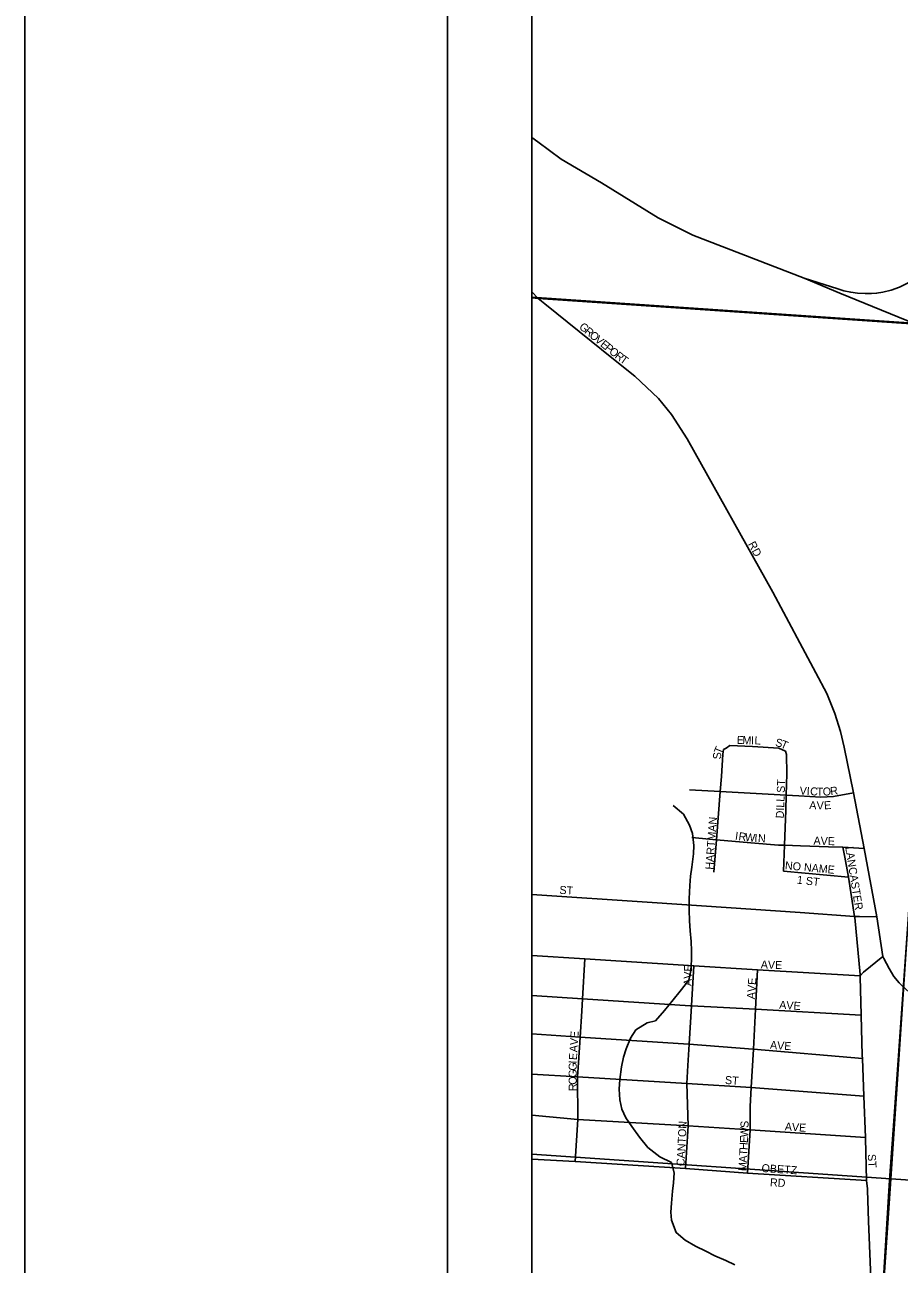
# Model space of a CAD drawing. Extents: x 0 to 34, y 0 to 22.
# Drawn here: x 2 to 3.034, y 15.158 to 16.625 of the extents above; entities that cross this region are included whole.
import ezdxf

# ---------------------------------------------------------------- set-up
doc = ezdxf.new("R2010")
doc.units = 0
for name, color, linetype in [('GM_X_City_Street', 7, 'Continuous'), ('GM_X_City_Street_Text', 7, 'Continuous'), ('GM_X_County_Road', 7, 'Continuous'), ('GM_X_Minor_River', 7, 'Continuous'), ('GM_X_Rail_Line', 7, 'Continuous'), ('GM_X_Section', 7, 'Continuous'), ('GM_X_Township', 7, 'Continuous'), ('SH_Border', 7, 'Continuous'), ('SH_Data', 7, 'Continuous')]:
    doc.layers.add(name, color=color, linetype=linetype)

msp = doc.modelspace()

# ---------------------------------------------------------------- linework, layer by layer
at = {"layer": 'GM_X_City_Street'}
for points in [[(2.6, 16.3085), (2.6075, 16.3008)], [(2.6, 16.3013), (2.6075, 16.3008), (3.1071, 16.2669), (3.4992, 16.2406), (3.5913, 16.2359), (3.8034, 16.221), (3.9012, 16.2137), (4.1012, 16.1998)], [(2.6075, 16.3008), (2.6152, 16.2945)], [(2.6152, 16.2945), (2.6963, 16.2291), (2.7217, 16.2089), (2.7498, 16.1825), (2.7649, 16.1636), (2.7838, 16.1347), (2.8848, 15.953), (2.9359, 15.8577), (2.949, 15.8334), (2.9582, 15.8094), (2.9649, 15.7883), (2.9693, 15.7698), (2.9805, 15.7157), (2.9931, 15.6496), (3.008, 15.5691), (3.0153, 15.522), (3.0164, 15.5198)], [(2.8151, 15.6218), (2.8182, 15.6601), (2.8228, 15.7172), (2.8242, 15.7349), (2.8257, 15.7615), (2.8268, 15.7668), (2.8298, 15.7684)], [(2.8298, 15.7684), (2.834, 15.7718), (2.8609, 15.7707), (2.892, 15.7686), (2.9, 15.7648)], [(2.8975, 15.6228), (2.8987, 15.6536), (2.9003, 15.695), (2.9008, 15.7129), (2.9016, 15.7382), (2.9012, 15.761), (2.9, 15.7648)], [(2.7864, 15.7192), (2.8228, 15.7172), (2.9008, 15.7129), (2.9157, 15.7121), (2.9419, 15.7107), (2.9567, 15.7115), (2.9805, 15.7157)], [(2.7892, 15.6627), (2.8182, 15.6601), (2.859, 15.6565), (2.8917, 15.6539), (2.8987, 15.6536), (2.9178, 15.6529), (2.9508, 15.6518), (2.9676, 15.6513), (2.9931, 15.6496)], [(2.9883, 15.5005), (2.9819, 15.568), (2.9817, 15.5693), (2.9744, 15.6159), (2.9737, 15.6204), (2.9702, 15.6394), (2.9676, 15.6513)], [(2.8975, 15.6228), (2.9744, 15.6159)], [(2.6, 15.5953), (2.7424, 15.5858), (2.9174, 15.5739), (2.9817, 15.5693), (2.9877, 15.5692)], [(2.9877, 15.5692), (3.008, 15.5691)], [(2.6, 15.5233), (2.6626, 15.5191), (2.7917, 15.5109), (2.8668, 15.5063), (2.9884, 15.499), (2.9921, 15.5034)], [(2.6512, 15.2793), (2.6543, 15.3289), (2.6539, 15.3794), (2.6551, 15.3961), (2.657, 15.4265), (2.659, 15.4572), (2.6599, 15.4717), (2.6626, 15.5191)], [(2.9921, 15.5034), (2.9923, 15.5036), (3.0153, 15.522)], [(3.0164, 15.5198), (3.0225, 15.5078), (3.0283, 15.4982), (3.0346, 15.4907), (3.0376, 15.4875), (3.0424, 15.4835), (3.0505, 15.4757), (3.0837, 15.4457), (3.143, 15.3917), (3.2033, 15.3361), (3.2871, 15.2577), (3.2952, 15.2496), (3.3057, 15.2376), (3.3571, 15.1717), (3.4014, 15.1172)], [(2.7816, 15.2712), (2.7847, 15.3214), (2.7831, 15.3718), (2.7844, 15.3931), (2.7859, 15.4181), (2.7887, 15.4637), (2.7887, 15.4641), (2.7917, 15.5109)], [(2.855, 15.2657), (2.8582, 15.3169), (2.8582, 15.3444), (2.8595, 15.3668), (2.8621, 15.4123), (2.8645, 15.4598), (2.8668, 15.5063)], [(2.9957, 15.2568), (2.9945, 15.3069), (2.9945, 15.3077), (2.9926, 15.3567), (2.9909, 15.4011), (2.9908, 15.4048), (2.9896, 15.4526), (2.9885, 15.4978), (2.9884, 15.499), (2.9883, 15.5005)], [(2.6, 15.4759), (2.6599, 15.4717), (2.7872, 15.4637), (2.7887, 15.4637), (2.8645, 15.4598), (2.9896, 15.4526)], [(2.6, 15.4306), (2.657, 15.4265), (2.7851, 15.4182), (2.7859, 15.4181), (2.8614, 15.4124), (2.8621, 15.4123), (2.9909, 15.4011)], [(2.6, 15.3826), (2.6539, 15.3794), (2.7831, 15.3718), (2.8595, 15.3668), (2.9926, 15.3567)], [(2.6, 15.3341), (2.6543, 15.3289), (2.7847, 15.3214), (2.8582, 15.3169), (2.9945, 15.3077)], [(2.6, 15.2821), (2.6512, 15.2793), (2.7816, 15.2712), (2.855, 15.2657), (2.9957, 15.2568)], [(2.9968, 15.2469), (2.9957, 15.2568)]]:
    msp.add_lwpolyline(points, dxfattribs=at)
at = {"layer": 'GM_X_County_Road'}
msp.add_lwpolyline([(2.9951, 14.9393), (3, 15.0013), (3.0025, 15.0426), (3.003, 15.0835), (3.0014, 15.132), (2.9982, 15.2087), (2.997, 15.2455), (2.9968, 15.2469)], dxfattribs=at)
at = {"layer": 'GM_X_Minor_River'}
for points in [[(2.767, 15.7008), (2.7794, 15.6904), (2.7865, 15.6774), (2.7898, 15.6676), (2.7916, 15.6535), (2.7911, 15.6436), (2.789, 15.6277), (2.7874, 15.6171), (2.7866, 15.6061), (2.786, 15.5902), (2.7859, 15.5769), (2.7865, 15.564), (2.7872, 15.5522), (2.7882, 15.5397), (2.7889, 15.5287), (2.7888, 15.5181), (2.7879, 15.5055), (2.7855, 15.4938), (2.7755, 15.481), (2.7671, 15.4708), (2.7568, 15.458), (2.746, 15.4459), (2.7365, 15.4434), (2.7228, 15.4351), (2.7167, 15.4253), (2.7113, 15.4128), (2.7085, 15.403), (2.7061, 15.3916), (2.7041, 15.3765), (2.7032, 15.3651), (2.7039, 15.3522), (2.7064, 15.3415), (2.7112, 15.3312), (2.718, 15.3206), (2.7273, 15.3083), (2.737, 15.2961), (2.7513, 15.285), (2.7649, 15.2781), (2.7681, 15.2661)], [(2.7643, 15.2195), (2.7649, 15.2302), (2.7663, 15.2442), (2.7676, 15.254), (2.7681, 15.2661)], [(2.8401, 15.1572), (2.8292, 15.1623), (2.8164, 15.1678), (2.8056, 15.1733), (2.7935, 15.1792), (2.7812, 15.1863), (2.7707, 15.1952), (2.7649, 15.2101), (2.7643, 15.2195)]]:
    msp.add_lwpolyline(points, dxfattribs=at)
at = {"layer": 'GM_X_Rail_Line'}
for points in [[(2.6, 16.4912), (2.6068, 16.486), (2.6346, 16.4655), (2.6824, 16.4375), (2.7492, 16.3962), (2.7904, 16.3756), (2.9219, 16.3246)], [(2.9219, 16.3246), (2.9617, 16.3122), (2.9691, 16.3097), (2.9772, 16.3081), (2.9852, 16.3071), (2.9944, 16.3065), (3.0018, 16.3066), (3.0078, 16.3069), (3.015, 16.3082), (3.025, 16.3105), (3.0348, 16.3143), (3.0458, 16.3197), (3.056, 16.3269), (3.0653, 16.335), (3.0722, 16.3421), (3.0807, 16.3527), (3.0865, 16.3633), (3.0919, 16.3759), (3.0958, 16.3882), (3.1005, 16.4143), (3.1042, 16.4365)], [(2.9219, 16.3246), (2.9644, 16.3072), (3.093, 16.2547)], [(3.0286, 15.3326), (3.0661, 15.8602), (3.093, 16.2547)], [(3.0069, 14.9926), (3.0232, 15.2571), (3.0286, 15.3326)]]:
    msp.add_lwpolyline(points, dxfattribs=at)
at = {"layer": 'GM_X_Section'}
for p, q in [((2.6, 17.3224), (2.6, 16.3022)), ((2.6, 16.3022), (2.6, 15.2882)), ((2.6, 15.2882), (2.6, 14.2769))]:
    msp.add_line(p, q, dxfattribs=at)
for points in [[(2.6, 16.3022), (3.0921, 16.2688), (3.1596, 17.2849), (2.6, 17.3224)], [(2.6, 15.2882), (3.0245, 15.259), (3.0921, 16.2688), (2.6, 16.3022)], [(2.6, 14.2769), (2.9564, 14.2543), (3.0245, 15.259), (2.6, 15.2882)]]:
    msp.add_lwpolyline(points, dxfattribs=at)
for points in [[(4.1014, 16.2018), (4.037, 15.2488), (4.0318, 15.1906), (3.0245, 15.259), (3.0921, 16.2688)], [(4.0318, 15.1906), (3.9642, 14.1968), (3.9626, 14.1817), (2.9564, 14.2543), (3.0245, 15.259)]]:
    msp.add_lwpolyline(points, close=True, dxfattribs=at)
at = {"layer": 'GM_X_Township'}
for points in [[(2.6, 16.3013), (2.6, 14.1), (3.9541, 14.1)], [(3.9541, 14.1), (3.9937, 14.7006), (4.0211, 15.0493), (4.0231, 15.0698), (4.0314, 15.1801), (4.0312, 15.1868), (4.0442, 15.3222), (4.0465, 15.365), (4.0719, 15.6825), (4.0775, 15.814), (4.0812, 15.875), (4.0887, 15.9581), (4.0927, 16.0027), (4.1038, 16.1956), (4.1041, 16.1996), (4.0997, 16.1999), (3.9012, 16.2137), (3.8034, 16.221), (3.5913, 16.2359), (3.4992, 16.2406), (3.1071, 16.2669), (2.6075, 16.3008), (2.6, 16.3013)]]:
    msp.add_lwpolyline(points, dxfattribs=at)
at = {"layer": 'SH_Border'}
msp.add_lwpolyline([(2, 21.5), (33.5, 21.5), (33.5, 0.5), (2, 0.5)], close=True, dxfattribs=at)
at = {"layer": 'SH_Data'}
for p, q in [((2.5, 21), (2.5, 14)), ((2.6, 20.9), (2.6, 14.1))]:
    msp.add_line(p, q, dxfattribs=at)

# ---------------------------------------------------------------- texts
at = {"layer": 'GM_X_City_Street_Text'}
for s, rotation, p in [('G', 320.5414, (2.655, 16.2658)), ('R', 320.5498, (2.6614, 16.2605)), ('O', 320.5414, (2.6672, 16.2557)), ('V', 320.5424, (2.6736, 16.2504)), ('E', 320.557, (2.6801, 16.2451)), ('P', 320.5722, (2.6852, 16.2409)), ('O', 320.9769, (2.6904, 16.2366)), ('R', 323.5873, (2.6973, 16.2311)), ('T', 324.4208, (2.7034, 16.2265)), ('RD', 297.8914, (2.8554, 16.0102)), ('E', 357.5401, (2.8422, 15.7737)), ('T', 67.605, (2.8237, 15.7609)), ('M', 357.6235, (2.8489, 15.7734)), ('I', 358.732, (2.8591, 15.773)), ('L', 359.7142, (2.8634, 15.7729)), ('S', 346.3215, (2.8873, 15.7712)), ('T', 337.7165, (2.8934, 15.7697)), ('S', 88.2784, (2.8237, 15.7552)), ('DILL ST', 87.7568, (2.8979, 15.6853)), ('V', 356.6323, (2.9165, 15.7137)), ('I', 356.631, (2.9248, 15.7132)), ('C', 356.6221, (2.9289, 15.7129)), ('T', 357.8199, (2.9366, 15.7125)), ('O', 3.3197, (2.9443, 15.7123)), ('R', 8.0582, (2.9535, 15.7128)), ('A', 356.7195, (2.9279, 15.6966)), ('V', 359.8237, (2.9368, 15.6961)), ('E', 3.4549, (2.9458, 15.6961)), ('HARTMAN', 85.9135, (2.8145, 15.6245)), ('I', 352.6364, (2.8399, 15.6603)), ('R', 352.6461, (2.844, 15.6598)), ('W', 354.0827, (2.8517, 15.6588)), ('I', 357.0322, (2.863, 15.6577)), ('N', 357.1012, (2.8672, 15.6574)), ('AVE', 358.0261, (2.933, 15.6545)), ('LANCASTER', 279.0051, (2.9706, 15.6514)), ('NO NAME', 354.644, (2.899, 15.6253)), ('1 ST', 353.6554, (2.9131, 15.6083)), ('ST', 356.4262, (2.6323, 15.5962)), ('AVE', 88.0261, (2.7887, 15.487)), ('AVE', 358.0186, (2.8706, 15.5079)), ('AVE', 86.0569, (2.8637, 15.4712)), ('AVE', 356.0569, (2.8923, 15.4603)), ('E', 86.1136, (2.6548, 15.425)), ('A', 86.1082, (2.6537, 15.4084)), ('V', 86.0841, (2.6543, 15.4167)), ('AVE', 356.0574, (2.8814, 15.4128)), ('E', 86.255, (2.6531, 15.3992)), ('G', 89.5847, (2.6529, 15.3869)), ('G', 89.9703, (2.6529, 15.3786)), ('I', 87.7705, (2.6529, 15.3951)), ('O', 89.9563, (2.6529, 15.3702)), ('ST', 356.4254, (2.8281, 15.3712)), ('R', 89.9757, (2.6529, 15.3627)), ('CANTON', 86.9852, (2.7804, 15.2737)), ('W', 87.7238, (2.8557, 15.3079)), ('S', 89.6942, (2.8562, 15.3191)), ('AVE', 356.0574, (2.8989, 15.3162)), ('H', 87.0991, (2.855, 15.2928)), ('E', 87.1021, (2.8554, 15.3011)), ('A', 87.0991, (2.8542, 15.2778)), ('T', 87.1021, (2.8546, 15.2861)), ('ST', 273.5746, (2.9973, 15.2879)), ('M', 87.103, (2.8537, 15.2678)), ('OBETZ', 356.1879, (2.8714, 15.267)), ('RD', 356.9884, (2.8814, 15.2501))]:
    msp.add_text(s, height=0.00947, rotation=rotation, dxfattribs=at).set_placement(p)

doc.saveas('drawing.dxf')
